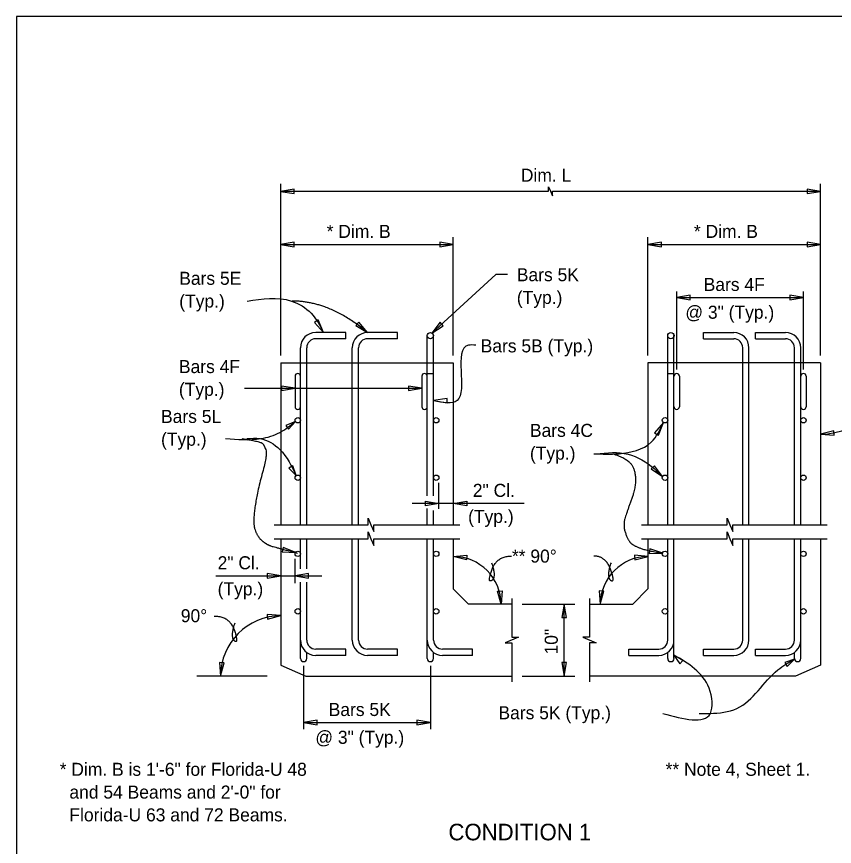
# Model space of a CAD drawing. Extents: x 120784.3 to 120844.8, y 120560 to 120604.3.
# Drawn here: x 120790.7 to 120800.18, y 120593.23 to 120602.85 of the extents above; entities that cross this region are included whole.
import ezdxf

# ---------------------------------------------------------------- set-up
doc = ezdxf.new("R2010")
doc.units = 0
for name, color, linetype in [('ActivePts-ConstElements', 7, 'Continuous'), ('AdhocPoint_dp', 7, 'Continuous'), ('PlotBorder_dp', 7, 'Continuous'), ('Rebar', 7, 'Continuous'), ('SheetBorder_dp', 7, 'Continuous')]:
    doc.layers.add(name, color=color, linetype=linetype)

# ---------------------------------------------------------------- blocks, each defined once
blk = doc.blocks.new('Terminator-Arrow')
at = {"layer": 'PlotBorder_dp'}
blk.add_lwpolyline([(0, 0), (-0.00041, 0.000069), (-0.00041, -0.000069)], close=True, dxfattribs=at)

msp = doc.modelspace()

# ---------------------------------------------------------------- linework, layer by layer
at = {"layer": 'ActivePts-ConstElements'}
msp.add_lwpolyline([(120790.7028, 120583.3868), (120821.4907, 120583.3868), (120821.4907, 120602.8464), (120790.7028, 120602.8464)], close=True, dxfattribs=at)
at = {"layer": 'AdhocPoint_dp'}
for p, q in [((120793.7624, 120598.8335), (120795.7624, 120598.8335)), ((120793.7624, 120598.8335), (120793.7624, 120596.9554)), ((120795.7625, 120598.8335), (120795.7625, 120596.9554)), ((120800.0174, 120598.8335), (120798.0174, 120598.8335)), ((120798.0175, 120598.8335), (120798.0175, 120596.9554)), ((120800.0174, 120598.8335), (120800.0174, 120596.9554)), ((120793.7624, 120596.7937), (120793.7624, 120595.3265)), ((120795.7625, 120596.7937), (120795.7625, 120596.2116)), ((120798.0175, 120596.7937), (120798.0175, 120596.2116)), ((120800.0174, 120596.7937), (120800.0174, 120595.3265)), ((120795.9392, 120596.0348), (120795.7625, 120596.2116)), ((120797.8407, 120596.0348), (120798.0175, 120596.2116)), ((120796.4398, 120596.0348), (120795.9392, 120596.0348)), ((120797.3401, 120596.0348), (120797.8407, 120596.0348)), ((120793.7624, 120595.3265), (120794.0541, 120595.2015)), ((120800.0174, 120595.3265), (120799.7258, 120595.2015)), ((120794.0541, 120595.2015), (120796.4398, 120595.2015)), ((120799.7258, 120595.2015), (120797.3401, 120595.2015))]:
    msp.add_line(p, q, dxfattribs=at)
at = {"layer": 'PlotBorder_dp'}
for p, q in [((120793.7625, 120598.9162), (120793.7625, 120600.9059)), ((120793.7625, 120598.9162), (120793.7625, 120600.9059)), ((120800.0175, 120598.9162), (120800.0175, 120600.9059)), ((120800.0175, 120598.9162), (120800.0175, 120600.9059)), ((120795.7625, 120598.9162), (120795.7625, 120600.29)), ((120795.7625, 120598.9162), (120795.7625, 120600.29)), ((120798.0174, 120598.9162), (120798.0174, 120600.29)), ((120798.0174, 120598.9162), (120798.0174, 120600.29)), ((120793.7623, 120600.2055), (120795.7623, 120600.2055)), ((120793.7623, 120600.2055), (120795.7623, 120600.2055)), ((120798.0173, 120600.2055), (120800.0173, 120600.2055)), ((120798.0173, 120600.2055), (120800.0173, 120600.2055)), ((120798.3508, 120598.7547), (120798.3508, 120599.661)), ((120798.3508, 120598.7547), (120798.3508, 120599.661)), ((120799.8195, 120598.7547), (120799.8195, 120599.661)), ((120799.8195, 120598.7547), (120799.8195, 120599.661)), ((120798.3508, 120599.5904), (120799.8195, 120599.5904)), ((120798.3508, 120599.5904), (120799.8195, 120599.5904)), ((120793.344, 120598.5373), (120793.9291, 120598.5373)), ((120793.344, 120598.5373), (120793.9291, 120598.5373)), ((120793.9291, 120598.5373), (120795.3979, 120598.5373)), ((120793.9291, 120598.5373), (120795.3979, 120598.5373)), ((120795.5958, 120597.1409), (120795.5958, 120597.4412)), ((120795.5958, 120597.1409), (120795.5958, 120597.4412)), ((120796.5847, 120597.2031), (120795.2857, 120597.2031)), ((120796.5847, 120597.2031), (120795.2857, 120597.2031)), ((120793.9291, 120596.2783), (120793.9291, 120596.5615)), ((120793.9291, 120596.2783), (120793.9291, 120596.5615)), ((120793.013, 120596.3637), (120794.2392, 120596.3637)), ((120793.013, 120596.3637), (120794.2392, 120596.3637)), ((120796.5609, 120596.0348), (120797.169, 120596.0348)), ((120796.5609, 120596.0348), (120797.169, 120596.0348)), ((120797.0482, 120595.2015), (120797.0482, 120596.0348)), ((120797.0482, 120595.2015), (120797.0482, 120596.0348)), ((120794.0281, 120595.3188), (120794.0281, 120594.5869)), ((120794.0281, 120595.3188), (120794.0281, 120594.5869)), ((120795.4968, 120595.3188), (120795.4968, 120594.5869)), ((120795.4968, 120595.3188), (120795.4968, 120594.5869)), ((120793.6046, 120595.2015), (120792.7913, 120595.2015)), ((120793.6046, 120595.2015), (120792.7913, 120595.2015)), ((120796.5609, 120595.2015), (120797.169, 120595.2015)), ((120796.5609, 120595.2015), (120797.169, 120595.2015)), ((120794.0281, 120594.6626), (120795.4968, 120594.6626)), ((120794.0281, 120594.6626), (120795.4968, 120594.6626))]:
    msp.add_line(p, q, dxfattribs=at)
for points in [[(120793.7623, 120600.8208), (120796.8673, 120600.8208), (120796.8673, 120600.8725), (120796.8898, 120600.8208), (120796.9123, 120600.7692), (120796.9123, 120600.8208), (120800.0173, 120600.8208)], [(120793.7623, 120600.8208), (120796.8673, 120600.8208), (120796.8673, 120600.8725), (120796.8898, 120600.8208), (120796.9123, 120600.7692), (120796.9123, 120600.8208), (120800.0173, 120600.8208)], [(120796.3898, 120599.8562), (120796.2568, 120599.8562), (120795.512, 120599.1776)], [(120796.3898, 120599.8562), (120796.2568, 120599.8562), (120795.512, 120599.1776)], [(120793.6868, 120596.9555), (120794.7747, 120596.9555), (120794.7747, 120597.033), (120794.8084, 120596.9555), (120794.8422, 120596.878), (120794.8422, 120596.9555), (120795.8381, 120596.9555)], [(120793.6868, 120596.9555), (120794.7747, 120596.9555), (120794.7747, 120597.033), (120794.8084, 120596.9555), (120794.8422, 120596.878), (120794.8422, 120596.9555), (120795.8381, 120596.9555)], [(120797.9418, 120596.9555), (120798.9345, 120596.9555), (120798.9345, 120597.033), (120798.9683, 120596.9555), (120799.002, 120596.878), (120799.002, 120596.9555), (120800.0931, 120596.9555)], [(120797.9418, 120596.9555), (120798.9345, 120596.9555), (120798.9345, 120597.033), (120798.9683, 120596.9555), (120799.002, 120596.878), (120799.002, 120596.9555), (120800.0931, 120596.9555)], [(120793.6868, 120596.7938), (120794.7747, 120596.7938), (120794.7747, 120596.8713), (120794.8084, 120596.7938), (120794.8422, 120596.7162), (120794.8422, 120596.7938), (120795.8381, 120596.7938)], [(120793.6868, 120596.7938), (120794.7747, 120596.7938), (120794.7747, 120596.8713), (120794.8084, 120596.7938), (120794.8422, 120596.7162), (120794.8422, 120596.7938), (120795.8381, 120596.7938)], [(120797.9418, 120596.7938), (120798.9345, 120596.7938), (120798.9345, 120596.8713), (120798.9683, 120596.7938), (120799.002, 120596.7162), (120799.002, 120596.7938), (120800.0931, 120596.7938)], [(120797.9418, 120596.7938), (120798.9345, 120596.7938), (120798.9345, 120596.8713), (120798.9683, 120596.7938), (120799.002, 120596.7162), (120799.002, 120596.7938), (120800.0931, 120596.7938)], [(120796.4398, 120596.1019), (120796.4398, 120595.6519), (120796.5173, 120595.6519), (120796.3623, 120595.5844), (120796.4398, 120595.5844), (120796.4398, 120595.1344)], [(120796.4398, 120596.1019), (120796.4398, 120595.6519), (120796.5173, 120595.6519), (120796.3623, 120595.5844), (120796.4398, 120595.5844), (120796.4398, 120595.1344)], [(120797.3401, 120596.1019), (120797.3401, 120595.6519), (120797.2626, 120595.6519), (120797.4176, 120595.5844), (120797.3401, 120595.5844), (120797.3401, 120595.1344)], [(120797.3401, 120596.1019), (120797.3401, 120595.6519), (120797.2626, 120595.6519), (120797.4176, 120595.5844), (120797.3401, 120595.5844), (120797.3401, 120595.1344)]]:
    msp.add_lwpolyline(points, dxfattribs=at)
for points in [[(120794.2597, 120599.1842), (120794.1977, 120599.33), (120794.1532, 120599.3014)], [(120794.2597, 120599.1842), (120794.1977, 120599.33), (120794.1532, 120599.3014)], [(120794.7696, 120599.1848), (120794.6666, 120599.3052), (120794.6327, 120599.2645)], [(120794.7696, 120599.1848), (120794.6666, 120599.3052), (120794.6327, 120599.2645)], [(120795.512, 120599.1776), (120795.6453, 120599.2632), (120795.6097, 120599.3024)], [(120795.512, 120599.1776), (120795.6453, 120599.2632), (120795.6097, 120599.3024)], [(120793.9291, 120598.5373), (120793.7729, 120598.5638), (120793.7729, 120598.5109)], [(120793.9291, 120598.5373), (120793.7729, 120598.5638), (120793.7729, 120598.5109)], [(120795.3979, 120598.5373), (120795.2417, 120598.5638), (120795.2417, 120598.5109)], [(120795.3979, 120598.5373), (120795.2417, 120598.5638), (120795.2417, 120598.5109)], [(120795.5333, 120598.3942), (120795.6895, 120598.3677), (120795.6895, 120598.4206)], [(120795.5333, 120598.3942), (120795.6895, 120598.3677), (120795.6895, 120598.4206)], [(120793.9322, 120598.1533), (120793.8215, 120598.1067), (120793.8523, 120598.0637)], [(120793.9322, 120598.1533), (120793.8215, 120598.1067), (120793.8523, 120598.0637)], [(120798.1988, 120598.1404), (120798.0934, 120598.022), (120798.1383, 120597.9939)], [(120798.1988, 120598.1404), (120798.0934, 120598.022), (120798.1383, 120597.9939)], [(120800.0174, 120598.0056), (120800.1753, 120597.9926), (120800.1708, 120598.0453)], [(120800.0174, 120598.0056), (120800.1753, 120597.9926), (120800.1708, 120598.0453)], [(120793.9408, 120597.5245), (120793.9016, 120597.638), (120793.8566, 120597.6101)], [(120793.9408, 120597.5245), (120793.9016, 120597.638), (120793.8566, 120597.6101)], [(120798.1872, 120597.5136), (120798.0919, 120597.6402), (120798.0556, 120597.6018)], [(120798.1872, 120597.5136), (120798.0919, 120597.6402), (120798.0556, 120597.6018)], [(120793.9372, 120596.6346), (120793.7896, 120596.692), (120793.7789, 120596.6401)], [(120793.9372, 120596.6346), (120793.7896, 120596.692), (120793.7789, 120596.6401)], [(120798.191, 120596.6271), (120798.0399, 120596.6749), (120798.0326, 120596.6225)], [(120798.191, 120596.6271), (120798.0399, 120596.6749), (120798.0326, 120596.6225)], [(120795.7624, 120596.5882), (120795.9203, 120596.6013), (120795.9158, 120596.5486)], [(120795.7624, 120596.5882), (120795.9203, 120596.6013), (120795.9158, 120596.5486)], [(120798.0196, 120596.5882), (120797.8617, 120596.6013), (120797.8662, 120596.5486)], [(120798.0196, 120596.5882), (120797.8617, 120596.6013), (120797.8662, 120596.5486)], [(120796.3172, 120596.0329), (120796.2761, 120596.1859), (120796.3288, 120596.1909)], [(120796.3172, 120596.0329), (120796.2761, 120596.1859), (120796.3288, 120596.1909)], [(120797.4648, 120596.0329), (120797.506, 120596.1859), (120797.4533, 120596.1909)], [(120797.4648, 120596.0329), (120797.506, 120596.1859), (120797.4533, 120596.1909)], [(120797.0482, 120596.0348), (120797.0218, 120595.8786), (120797.0747, 120595.8786)], [(120797.0482, 120596.0348), (120797.0218, 120595.8786), (120797.0747, 120595.8786)], [(120793.7645, 120595.9013), (120793.6067, 120595.9143), (120793.6112, 120595.8616)], [(120793.7645, 120595.9013), (120793.6067, 120595.9143), (120793.6112, 120595.8616)], [(120798.3195, 120595.4442), (120798.3864, 120595.3444), (120798.4228, 120595.3828)], [(120798.3195, 120595.4442), (120798.3864, 120595.3444), (120798.4228, 120595.3828)], [(120799.716, 120595.3981), (120799.6034, 120595.3564), (120799.6322, 120595.312)], [(120799.716, 120595.3981), (120799.6034, 120595.3564), (120799.6322, 120595.312)], [(120793.0651, 120595.2012), (120793.1062, 120595.3542), (120793.0535, 120595.3592)], [(120793.0651, 120595.2012), (120793.1062, 120595.3542), (120793.0535, 120595.3592)], [(120797.0482, 120595.2015), (120797.0747, 120595.3577), (120797.0218, 120595.3577)], [(120797.0482, 120595.2015), (120797.0747, 120595.3577), (120797.0218, 120595.3577)]]:
    msp.add_lwpolyline(points, close=True, dxfattribs=at)
for centre, radius, start, end in [((120800.0149, 120598.8335), 0.8279, 270.17686, 0), ((120800.0149, 120598.8335), 0.8279, 270.17686, 0), ((120795.7581, 120596.029), 0.5592, 0.39914, 89.54996), ((120795.7581, 120596.029), 0.5592, 0.39914, 89.54996), ((120798.024, 120596.029), 0.5592, 90.45004, 179.60086), ((120798.024, 120596.029), 0.5592, 90.45004, 179.60086), ((120793.77, 120595.1962), 0.705, 90.45004, 179.60086), ((120793.77, 120595.1962), 0.705, 90.45004, 179.60086)]:
    msp.add_arc(centre, radius, start, end, dxfattribs=at)
for points in [[(120793.3728, 120599.5489), (120793.8872, 120599.5489), (120794.1173, 120599.4063), (120794.2597, 120599.1842)], [(120793.3728, 120599.5489), (120793.8872, 120599.5489), (120794.1173, 120599.4063), (120794.2597, 120599.1842)], [(120796.023, 120599.0364), (120795.939, 120599.0364), (120795.8066, 120598.3941), (120795.5333, 120598.3941)], [(120796.023, 120599.0364), (120795.939, 120599.0364), (120795.8066, 120598.3941), (120795.5333, 120598.3941)], [(120793.1249, 120597.954), (120793.5338, 120597.954), (120793.753, 120598.0253), (120793.9322, 120598.1533)], [(120793.1249, 120597.954), (120793.5338, 120597.954), (120793.753, 120598.0253), (120793.9322, 120598.1533)], [(120797.3888, 120597.7785), (120797.6834, 120597.7785), (120798.0563, 120597.9128), (120798.1988, 120598.1403)], [(120797.3888, 120597.7785), (120797.6834, 120597.7785), (120798.0563, 120597.9128), (120798.1988, 120598.1403)], [(120793.3695, 120597.954), (120793.5229, 120597.954), (120793.753, 120597.8279), (120793.9408, 120597.5245)], [(120793.3695, 120597.954), (120793.5229, 120597.954), (120793.753, 120597.8279), (120793.9408, 120597.5245)], [(120797.4174, 120597.7785), (120797.7878, 120597.7735), (120798.0886, 120597.6069), (120798.1872, 120597.5136)], [(120797.4174, 120597.7785), (120797.7878, 120597.7735), (120798.0886, 120597.6069), (120798.1872, 120597.5136)], [(120798.1897, 120594.767), (120798.7405, 120594.7678), (120798.7258, 120595.0593), (120798.3195, 120595.4442)], [(120798.1897, 120594.767), (120798.7405, 120594.7678), (120798.7258, 120595.0593), (120798.3195, 120595.4442)], [(120798.6106, 120594.7676), (120798.7353, 120594.7677), (120799.0472, 120594.8256), (120799.5221, 120595.272), (120799.716, 120595.398)], [(120798.6106, 120594.7676), (120798.7353, 120594.7677), (120799.0472, 120594.8256), (120799.5221, 120595.272), (120799.716, 120595.398)]]:
    msp.add_spline(points, degree=3, dxfattribs=at)
for points in [[(120794.7697, 120599.1842), (120794.3324, 120599.5487), (120793.8951, 120599.5487)], [(120794.7697, 120599.1842), (120794.3324, 120599.5487), (120793.8951, 120599.5487)], [(120793.313, 120597.954), (120793.5277, 120597.9215), (120793.5741, 120597.875), (120793.6082, 120597.7634), (120793.4905, 120597.3388), (120793.4378, 120596.9762), (120793.4905, 120596.8212), (120793.5927, 120596.7282), (120793.7073, 120596.691), (120793.9584, 120596.6271)], [(120793.313, 120597.954), (120793.5277, 120597.9215), (120793.5741, 120597.875), (120793.6082, 120597.7634), (120793.4905, 120597.3388), (120793.4378, 120596.9762), (120793.4905, 120596.8212), (120793.5927, 120596.7282), (120793.7073, 120596.691), (120793.9584, 120596.6271)], [(120797.6169, 120597.7758), (120797.7832, 120597.7226), (120797.8736, 120597.5799), (120797.8736, 120597.3753), (120797.7785, 120597.1184), (120797.7261, 120596.9471), (120797.788, 120596.7711), (120797.8498, 120596.714), (120798.0115, 120596.6521), (120798.191, 120596.6271)], [(120797.6169, 120597.7758), (120797.7832, 120597.7226), (120797.8736, 120597.5799), (120797.8736, 120597.3753), (120797.7785, 120597.1184), (120797.7261, 120596.9471), (120797.788, 120596.7711), (120797.8498, 120596.714), (120798.0115, 120596.6521), (120798.191, 120596.6271)], [(120796.2063, 120596.5155), (120796.2636, 120596.3436), (120796.1528, 120596.2749), (120796.2655, 120596.5919), (120796.4371, 120596.5919)], [(120796.2063, 120596.5155), (120796.2636, 120596.3436), (120796.1528, 120596.2749), (120796.2655, 120596.5919), (120796.4371, 120596.5919)], [(120797.5896, 120596.5155), (120797.5323, 120596.3436), (120797.6431, 120596.2749), (120797.5304, 120596.5919), (120797.3908, 120596.5919)], [(120797.5896, 120596.5155), (120797.5323, 120596.3436), (120797.6431, 120596.2749), (120797.5304, 120596.5919), (120797.3908, 120596.5919)], [(120793.2301, 120595.8162), (120793.1729, 120595.6443), (120793.2836, 120595.5756), (120793.171, 120595.8926), (120792.9934, 120595.8926)], [(120793.2301, 120595.8162), (120793.1729, 120595.6443), (120793.2836, 120595.5756), (120793.171, 120595.8926), (120792.9934, 120595.8926)]]:
    msp.add_open_spline(points, degree=2, dxfattribs=at)
at = {"layer": 'Rebar'}
for p, q in [((120794.5166, 120599.1842), (120794.1687, 120599.1842)), ((120794.5166, 120599.1113), (120794.5166, 120599.1842)), ((120795.1176, 120599.1842), (120794.7697, 120599.1842)), ((120795.1176, 120599.1113), (120795.1176, 120599.1842)), ((120795.4604, 120597.2886), (120795.4604, 120599.1477)), ((120795.5333, 120597.2886), (120795.5333, 120599.1477)), ((120798.2466, 120596.9554), (120798.2466, 120599.1477)), ((120798.3195, 120596.9554), (120798.3195, 120599.1477)), ((120798.6632, 120599.1842), (120799.0111, 120599.1842)), ((120798.6632, 120599.1113), (120798.6632, 120599.1842)), ((120799.2633, 120599.1842), (120799.6112, 120599.1842)), ((120799.2633, 120599.1113), (120799.2633, 120599.1842)), ((120794.5166, 120599.1113), (120794.1687, 120599.1113)), ((120795.1176, 120599.1113), (120794.7697, 120599.1113)), ((120798.6632, 120599.1113), (120799.0111, 120599.1113)), ((120799.2633, 120599.1113), (120799.6112, 120599.1113)), ((120793.9916, 120596.9554), (120793.9916, 120599.0071)), ((120794.0645, 120596.9554), (120794.0645, 120599.0071)), ((120794.5926, 120596.9554), (120794.5926, 120599.0071)), ((120794.6655, 120596.9554), (120794.6655, 120599.0071)), ((120799.1153, 120596.9554), (120799.1153, 120599.0071)), ((120799.1882, 120596.9554), (120799.1882, 120599.0071)), ((120799.7154, 120596.9554), (120799.7154, 120599.0071)), ((120799.7883, 120596.9554), (120799.7883, 120599.0071)), ((120793.9291, 120598.6772), (120793.9291, 120598.3231)), ((120795.3979, 120598.6772), (120795.3979, 120598.3231)), ((120795.4604, 120598.7085), (120795.5333, 120598.7085)), ((120798.2466, 120598.7085), (120798.3195, 120598.7085)), ((120798.382, 120598.6772), (120798.382, 120598.3231)), ((120799.8508, 120598.6772), (120799.8508, 120598.3231)), ((120795.4604, 120596.9554), (120795.4604, 120597.1418)), ((120795.5333, 120596.9554), (120795.5333, 120597.1195)), ((120793.9916, 120596.4428), (120793.9916, 120596.7937)), ((120794.0645, 120596.4428), (120794.0645, 120596.7937)), ((120794.5926, 120595.6182), (120794.5926, 120596.7937)), ((120794.6655, 120595.6182), (120794.6655, 120596.7937)), ((120795.4604, 120595.4046), (120795.4604, 120596.7937)), ((120795.5333, 120595.6182), (120795.5333, 120596.7937)), ((120798.2466, 120595.6182), (120798.2466, 120596.7937)), ((120798.3195, 120595.4046), (120798.3195, 120596.7937)), ((120799.1153, 120595.6182), (120799.1153, 120596.7937)), ((120799.1882, 120595.6182), (120799.1882, 120596.7937)), ((120799.7154, 120595.6182), (120799.7154, 120596.7937)), ((120799.7883, 120595.4046), (120799.7883, 120596.7937)), ((120793.9916, 120595.4046), (120793.9916, 120596.2903)), ((120794.0645, 120595.6182), (120794.0645, 120596.2903)), ((120794.5166, 120595.514), (120794.1687, 120595.514)), ((120794.5166, 120595.4411), (120794.5166, 120595.514)), ((120795.1176, 120595.514), (120794.7697, 120595.514)), ((120795.1176, 120595.4411), (120795.1176, 120595.514)), ((120795.9854, 120595.514), (120795.6375, 120595.514)), ((120795.9854, 120595.4411), (120795.9854, 120595.514)), ((120797.7945, 120595.514), (120798.1424, 120595.514)), ((120797.7945, 120595.4411), (120797.7945, 120595.514)), ((120798.6632, 120595.514), (120799.0111, 120595.514)), ((120798.6632, 120595.4411), (120798.6632, 120595.514)), ((120799.2633, 120595.514), (120799.6112, 120595.514)), ((120799.2633, 120595.4411), (120799.2633, 120595.514)), ((120794.0645, 120595.4046), (120794.0645, 120595.4749)), ((120794.5166, 120595.4411), (120794.1687, 120595.4411)), ((120795.1176, 120595.4411), (120794.7697, 120595.4411)), ((120795.5333, 120595.4046), (120795.5333, 120595.4749)), ((120795.9854, 120595.4411), (120795.6375, 120595.4411)), ((120797.7945, 120595.4411), (120798.1424, 120595.4411)), ((120798.2466, 120595.4046), (120798.2466, 120595.4749)), ((120798.6632, 120595.4411), (120799.0111, 120595.4411)), ((120799.2633, 120595.4411), (120799.6112, 120595.4411)), ((120799.7154, 120595.4046), (120799.7154, 120595.4749))]:
    msp.add_line(p, q, dxfattribs=at)
for centre, radius in [((120795.4968, 120599.1477), 0.0365), ((120798.2831, 120599.1477), 0.0365), ((120793.9604, 120598.1668), 0.0312), ((120795.5645, 120598.1668), 0.0312), ((120798.2154, 120598.1668), 0.0312), ((120799.8195, 120598.1668), 0.0312), ((120793.9604, 120597.5002), 0.0312), ((120795.5645, 120597.5002), 0.0312), ((120798.2154, 120597.5002), 0.0312), ((120799.8195, 120597.5002), 0.0312), ((120793.9604, 120596.6181), 0.0312), ((120795.5645, 120596.6181), 0.0312), ((120798.2154, 120596.6181), 0.0312), ((120799.8195, 120596.6181), 0.0312), ((120793.9604, 120595.9515), 0.0312), ((120795.5645, 120595.9515), 0.0312), ((120798.2154, 120595.9515), 0.0312), ((120799.8195, 120595.9515), 0.0312)]:
    msp.add_circle(centre, radius, dxfattribs=at)
for centre, radius, start, end in [((120794.1687, 120599.0071), 0.1771, 90, 180), ((120794.7697, 120599.0071), 0.1771, 90, 180), ((120799.0111, 120599.0071), 0.1771, 0, 90), ((120799.6112, 120599.0071), 0.1771, 0, 90), ((120794.1687, 120599.0071), 0.1042, 90, 180), ((120794.7697, 120599.0071), 0.1042, 90, 180), ((120799.0111, 120599.0071), 0.1042, 0, 90), ((120799.6112, 120599.0071), 0.1042, 0, 90), ((120793.9604, 120598.6772), 0.0312, 0, 180), ((120795.4291, 120598.6772), 0.0312, 0, 180), ((120798.3508, 120598.6772), 0.0312, 0, 180), ((120799.8195, 120598.6772), 0.0312, 0, 180), ((120793.9604, 120598.3231), 0.0312, 180, 0), ((120795.4291, 120598.3231), 0.0312, 180, 0), ((120798.3508, 120598.3231), 0.0312, 180, 0), ((120799.8195, 120598.3231), 0.0312, 180, 0), ((120794.1687, 120595.6182), 0.1771, 180, 270), ((120794.1687, 120595.6182), 0.1042, 180, 270), ((120794.7697, 120595.6182), 0.1771, 180, 270), ((120794.7697, 120595.6182), 0.1042, 180, 270), ((120795.6375, 120595.6182), 0.1771, 180, 270), ((120795.6375, 120595.6182), 0.1042, 180, 270), ((120798.1424, 120595.6182), 0.1042, 270, 360), ((120798.1424, 120595.6182), 0.1771, 270, 360), ((120799.0111, 120595.6182), 0.1042, 270, 0), ((120799.0111, 120595.6182), 0.1771, 270, 0), ((120799.6112, 120595.6182), 0.1042, 270, 360), ((120799.6112, 120595.6182), 0.1771, 270, 360), ((120794.0281, 120595.4046), 0.0365, 180, 0), ((120795.4968, 120595.4046), 0.0365, 180, 0), ((120798.2831, 120595.4046), 0.0365, 180, 0), ((120799.7518, 120595.4046), 0.0365, 180, 0)]:
    msp.add_arc(centre, radius, start, end, dxfattribs=at)

# ---------------------------------------------------------------- block references
at = {"layer": 'PlotBorder_dp', "xscale": 381, "rotation": 180}
for p, yscale in [((120793.7622, 120600.8203), 384.0238095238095), ((120793.7622, 120600.8203), 384.0238095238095), ((120793.7622, 120600.2051), 384.0238095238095), ((120793.7622, 120600.2051), 384.0238095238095), ((120798.0172, 120600.2051), 384.0238095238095), ((120798.0172, 120600.2051), 384.0238095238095), ((120798.3506, 120599.5902), 384.0238095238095), ((120798.3506, 120599.5902), 384.0238095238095), ((120795.7623, 120597.2027), -384.0238095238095), ((120795.7623, 120597.2027), -384.0238095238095), ((120793.929, 120596.3632), 384.0238095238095), ((120793.929, 120596.3632), 384.0238095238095), ((120794.028, 120594.6622), 384.0238095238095), ((120794.028, 120594.6622), 384.0238095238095)]:
    msp.add_blockref('Terminator-Arrow', p, dxfattribs=dict(at, yscale=yscale))
at = {"layer": 'PlotBorder_dp', "xscale": 381}
for p, yscale in [((120800.0172, 120600.8204), 384.0238095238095), ((120800.0172, 120600.8204), 384.0238095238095), ((120795.7622, 120600.2051), 384.0238095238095), ((120795.7622, 120600.2051), 384.0238095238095), ((120800.0172, 120600.2051), 384.0238095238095), ((120800.0172, 120600.2051), 384.0238095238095), ((120799.8194, 120599.5902), 384.0238095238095), ((120799.8194, 120599.5902), 384.0238095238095), ((120795.5957, 120597.2027), -384.0238095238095), ((120795.5957, 120597.2027), -384.0238095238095), ((120793.7623, 120596.3632), 384.0238095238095), ((120793.7623, 120596.3632), 384.0238095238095), ((120795.4967, 120594.6622), 384.0238095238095), ((120795.4967, 120594.6622), 384.0238095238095)]:
    msp.add_blockref('Terminator-Arrow', p, dxfattribs=dict(at, yscale=yscale))

# ---------------------------------------------------------------- texts
at = {"layer": 'PlotBorder_dp'}
for s, p in [('Bars 5K', (120796.4985, 120599.7786)), ('Bars 5E', (120792.587, 120599.737)), ('(Typ.)', (120792.587, 120599.473)), ('(Typ.)', (120796.4985, 120599.5146)), ('Bars 4F', (120792.5835, 120598.7134)), ('(Typ.)', (120792.5835, 120598.4494)), ('Bars 5L', (120792.3763, 120598.1353)), ('Bars 4C', (120796.6503, 120597.9737)), ('(Typ.)', (120792.3763, 120597.8713)), ('(Typ.)', (120796.6503, 120597.7097)), ('* Dim. B is 1\'-6" for Florida-U 48', (120791.2021, 120594.0445)), ('** Note 4, Sheet 1.', (120798.222, 120594.0445)), ('  and 54 Beams and 2\'-0" for ', (120791.2021, 120593.7805)), ('  Florida-U 63 and 72 Beams.', (120791.2021, 120593.5165))]:
    msp.add_text(s, height=0.1512, dxfattribs=at).set_placement(p)
at = {"layer": 'SheetBorder_dp'}
for s, height, p in [('Dim. L', 0.1512, (120796.545, 120600.932)), ('* Dim. B', 0.1512, (120794.2955, 120600.2807)), ('* Dim. B', 0.1512, (120798.5505, 120600.2807)), ('Bars 4F', 0.1512, (120798.6633, 120599.6657)), ('@ 3" (Typ.)', 0.1512, (120798.4511, 120599.3436)), ('Bars 5B (Typ.)', 0.1512, (120796.0797, 120598.9535)), ('2" Cl.', 0.1512, (120795.9888, 120597.2783)), ('(Typ.)', 0.1512, (120795.934, 120596.9759)), ('** 90°', 0.1512, (120796.4417, 120596.5159)), ('2" Cl.', 0.1512, (120793.032, 120596.4389)), ('(Typ.)', 0.1512, (120793.032, 120596.1364)), ('90°', 0.1512, (120792.6051, 120595.8249)), ('Bars 5K', 0.1512, (120794.3189, 120594.7378)), ('Bars 5K (Typ.)', 0.1512, (120796.2858, 120594.7003)), ('@ 3" (Typ.)', 0.1512, (120794.164, 120594.4155)), ('CONDITION 1', 0.192, (120795.7058, 120593.2968))]:
    msp.add_text(s, height=height, dxfattribs=at).set_placement(p)
msp.add_text('10"', height=0.1512, rotation=90, dxfattribs=at).set_placement((120796.9726, 120595.4512))

doc.saveas('drawing.dxf')
